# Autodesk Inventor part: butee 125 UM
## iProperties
Author: Administrateur
Created: 2002-02
Part Number: butee 125 UM
Material: Par défaut
Document SubType Name: Modélisation
Designer: Administrateur
Control State: 0
Master: False
Checked Out: False
PropertySet Name: Design Tracking Control
Shininess: 41.0
Angle Display Precision: 2
Document Length Units: 11269
Document Angle Units: 11283
Document Time Units: 11279
Document Mass Units: 11290
Document Length Units Precision: 3
Document Angle Units Precision: 2
Compacted: False
PropertySet Name: _Private Model Information
Density: 0.0
Volumn: 0.0
Area: 0.0
PropertySet Name: Model Information
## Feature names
1. Extrusion1
2. Perçage1 [Hole]
